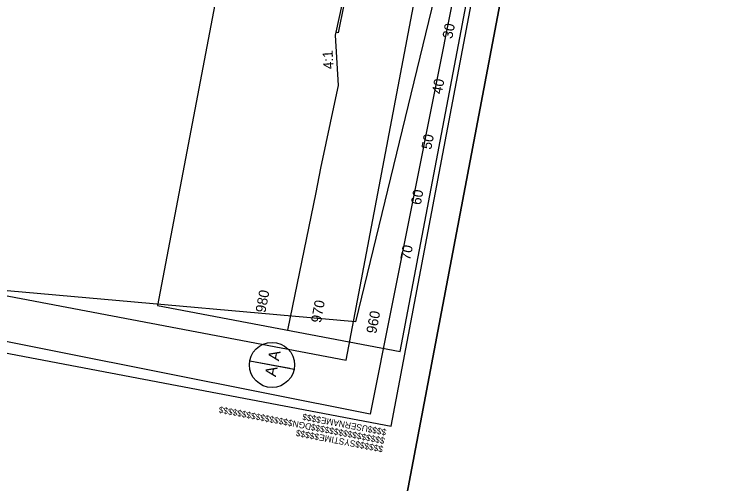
# Model space of a CAD drawing. Extents: x 1615680 to 1617075, y 898420 to 901168.
# Drawn here: x 1616432 to 1617075, y 899419 to 899835 of the extents above; entities that cross this region are included whole.
import ezdxf

# ---------------------------------------------------------------- set-up
doc = ezdxf.new("R2010")
doc.units = 0
for name, color, linetype in [('Default', 7, 'Continuous'), ('DEV BORDER CELL', 7, 'Continuous'), ('Exist XS Ground Line', 7, 'Continuous'), ('Prop Conc 4in Sidewalk', 7, 'Continuous'), ('Prop XS Elevation Labels', 7, 'Continuous'), ('Prop XS Finish Grade', 7, 'Continuous'), ('Prop XS Label Text', 7, 'Continuous'), ('Prop XS Offset Labels', 7, 'Continuous'), ('Scratch_Level_0', 7, 'Continuous'), ('Scratch_Level_9', 7, 'Continuous'), ('Sheet Clip Boundary CELL', 7, 'Continuous'), ('Sheet Cross Section CELL', 7, 'Continuous'), ('Sheet Plot Border Outside CELL', 7, 'Continuous')]:
    doc.layers.add(name, color=color, linetype=linetype)

msp = doc.modelspace()

# ---------------------------------------------------------------- linework, layer by layer
at = {"layer": 'Default'}
for p, q in [((1616641.15, 899527.69), (1616676.55, 899520.97)), ((1616641.15, 899527.68), (1616680.44, 899520.23))]:
    msp.add_line(p, q, dxfattribs=at)
msp.add_circle((1616660.8, 899523.96), 20, dxfattribs=at)
at = {"layer": 'DEV BORDER CELL'}
msp.add_line((1616766.32, 899469.67), (1616766.32, 899469.67), dxfattribs=at)
msp.add_lwpolyline([(1616014.55, 901139.21), (1615734.74, 899665.53), (1616766.32, 899469.67), (1617046.12, 900943.35)], close=True, dxfattribs=at)
at = {"layer": 'Exist XS Ground Line'}
msp.add_lwpolyline([(1616674.94, 899554.66), (1616699.81, 899676.84), (1616704.2, 899698.26), (1616717.32, 899760.65), (1616719.78, 899771.67)], dxfattribs=at)
at = {"layer": 'Prop Conc 4in Sidewalk'}
msp.add_lwpolyline([(1616722.88, 899843.32), (1616724.53, 899843.06), (1616719.35, 899818.49), (1616717.73, 899818.85), (1616722.88, 899843.32)], dxfattribs=at)
at = {"layer": 'Prop XS Finish Grade'}
for points in [[(1616717.21, 899816.4), (1616717.73, 899818.85), (1616717.73, 899818.85)], [(1616719.78, 899771.67), (1616719.78, 899771.67), (1616717.21, 899816.4)]]:
    msp.add_lwpolyline(points, dxfattribs=at)
at = {"layer": 'Scratch_Level_0'}
msp.add_lwpolyline([(1616054.34, 901080.76), (1615793.19, 899705.33), (1616726.52, 899528.12), (1616890.46, 900391.55), (1616774.26, 900413.61), (1616871.48, 900925.61)], close=True, dxfattribs=at)
at = {"layer": 'Sheet Clip Boundary CELL'}
for points in [[(1616176.29, 901060.7), (1616848.46, 900914.27), (1616896.28, 900812.91), (1616872.94, 900688.21), (1616835.87, 900695.21), (1616753.94, 900262.18), (1616898.09, 900233.43), (1616734.79, 899562.1), (1616202.98, 899609.43), (1616198.71, 899647.14), (1615822.69, 899825.07), (1616054.34, 901080.76)], [(1616176.29, 901060.7), (1616914, 900899.99), (1616896.28, 900812.91), (1616872.94, 900688.21), (1616835.87, 900695.21), (1616753.94, 900262.18), (1616898.09, 900233.43), (1616747.89, 899480.25), (1615915.8, 899646.19), (1615751.76, 899738.03), (1615981.58, 900932.46), (1616145.94, 900899.57)]]:
    msp.add_lwpolyline(points, close=True, dxfattribs=at)
at = {"layer": 'Sheet Cross Section CELL'}
for p, q in [((1616723.15, 900439.56), (1616559.31, 899576.61)), ((1616774.52, 899535.75), (1616938.37, 900398.7)), ((1616559.31, 899576.61), (1616774.52, 899535.75))]:
    msp.add_line(p, q, dxfattribs=at)
at = {"layer": 'Sheet Plot Border Outside CELL'}
for points in [[(1616760.47, 899304.87), (1615679.78, 899510.06), (1615994.65, 901168.43), (1617075.34, 900963.24)], [(1616760.47, 899304.87), (1617075.34, 900963.24), (1615994.65, 901168.43), (1615679.78, 899510.06)]]:
    msp.add_lwpolyline(points, close=True, dxfattribs=at)

# ---------------------------------------------------------------- texts
at = {"layer": 'Default'}
for p in [(1616666.83, 899527.06), (1616664.16, 899513)]:
    msp.add_text('A', height=10, rotation=79.25306, dxfattribs=at).set_placement(p)
at = {"layer": 'DEV BORDER CELL'}
for s, p in [('$$$$$$$$$$$$$$$$DGN$$$$$$$$$$$$$$$$', (1616761.22, 899459.32)), ('$$$$USERNAME$$$$', (1616762.63, 899466.77)), ('$$$$$$SYSTIME$$$$$', (1616759.8, 899451.87))]:
    msp.add_text(s, height=5.584, rotation=169.24937, dxfattribs=at).set_placement(p)
at = {"layer": 'Prop XS Elevation Labels'}
for s, p in [('980', (1616654.85, 899569.73)), ('970', (1616704.04, 899560.75)), ('960', (1616753.12, 899551.22))]:
    msp.add_text(s, height=9, rotation=79.24937, dxfattribs=at).set_placement(p)
at = {"layer": 'Prop XS Label Text'}
msp.add_text('4:1', height=9, rotation=93.28561, dxfattribs=at).set_placement((1616715.43, 899786.35))
at = {"layer": 'Prop XS Offset Labels'}
for s, p in [('30', (1616820.63, 899812.68)), ('40', (1616811.3, 899763.56)), ('50', (1616801.97, 899714.44)), ('60', (1616792.65, 899665.31)), ('70', (1616783.32, 899616.19))]:
    msp.add_text(s, height=9, rotation=79.24937, dxfattribs=at).set_placement(p)
at = {"layer": 'Scratch_Level_9'}
msp.add_text('X', height=0.00125, rotation=79.24937, dxfattribs=at).set_placement((1616717.73, 899818.85))

doc.saveas('drawing.dxf')
